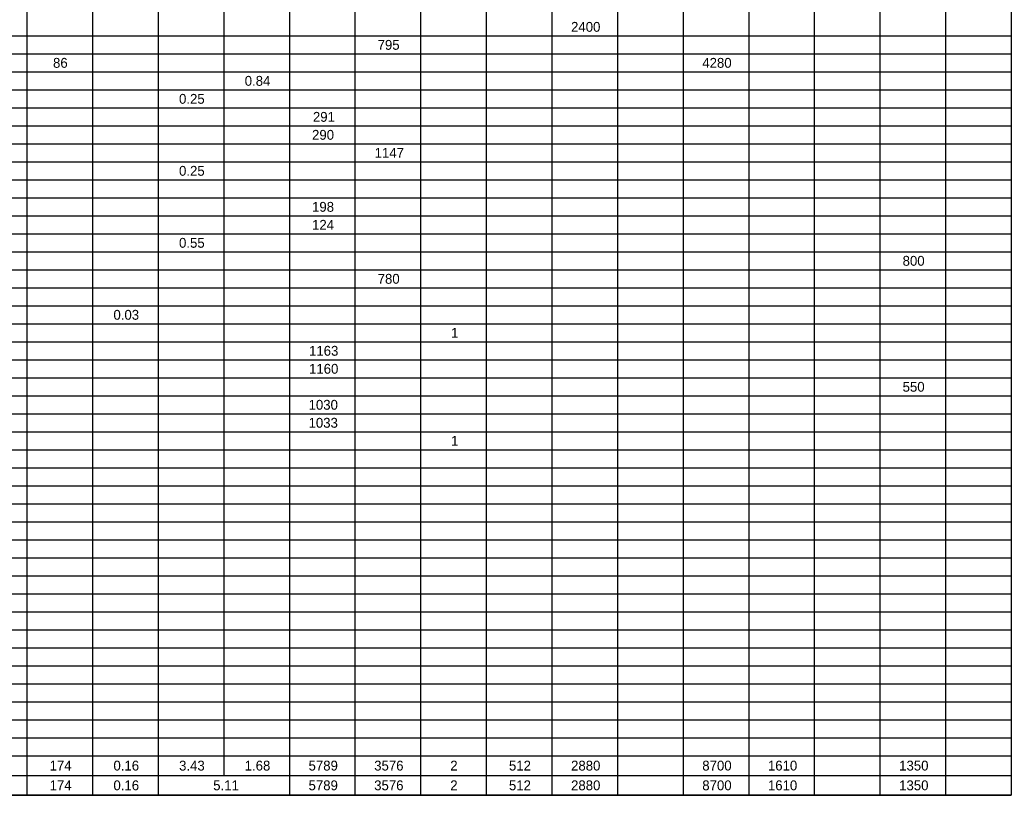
# Model space of a CAD drawing. Extents: x 91011267 to 91022583, y 37007614 to 37014266.
# Drawn here: x 91012046 to 91012802, y 37007614 to 37008206 of the extents above; entities that cross this region are included whole.
import ezdxf

# ---------------------------------------------------------------- set-up
doc = ezdxf.new("R2010")
doc.units = 0
doc.layers.add('SC_Scratch2', color=7, linetype='Continuous')
doc.layers.add('SH_Data', color=7, linetype='Continuous')

msp = doc.modelspace()

# ---------------------------------------------------------------- linework, layer by layer
at = {"layer": 'SC_Scratch2'}
msp.add_lwpolyline([(91011277.35, 37008663.81), (91012802.35, 37008663.81), (91012802.35, 37007613.81), (91011277.35, 37007613.81)], close=True, dxfattribs=at)
at = {"layer": 'SH_Data'}
for p, q in [((91012051.05, 37008289.61), (91012051.05, 37008083.53)), ((91012101.14, 37008289.61), (91012101.14, 37008083.53)), ((91012151.23, 37008289.61), (91012151.23, 37008083.53)), ((91012201.31, 37008289.61), (91012201.31, 37008083.53)), ((91012251.4, 37008289.61), (91012251.4, 37008083.53)), ((91012301.49, 37008289.61), (91012301.49, 37008083.53)), ((91012351.57, 37008289.61), (91012351.57, 37008083.53)), ((91012401.66, 37008289.61), (91012401.66, 37008083.53)), ((91012451.75, 37008289.61), (91012451.75, 37008083.53)), ((91012501.83, 37008289.61), (91012501.83, 37008083.53)), ((91012551.92, 37008289.61), (91012551.92, 37008083.53)), ((91012602, 37008289.61), (91012602, 37008083.53)), ((91012652.09, 37008289.61), (91012652.09, 37008083.53)), ((91012702.18, 37008289.61), (91012702.18, 37008083.53)), ((91012752.26, 37008289.61), (91012752.26, 37008083.53)), ((91012802.35, 37008289.61), (91012802.35, 37008083.53)), ((91012000.97, 37008193.44), (91012551.92, 37008193.44)), ((91012551.92, 37008193.44), (91012602, 37008193.44)), ((91012602, 37008193.44), (91012652.09, 37008193.44)), ((91012652.09, 37008193.44), (91012702.18, 37008193.44)), ((91012702.18, 37008193.44), (91012802.35, 37008193.44)), ((91012000.97, 37008179.7), (91012551.92, 37008179.7)), ((91012551.92, 37008179.7), (91012602, 37008179.7)), ((91012602, 37008179.7), (91012652.09, 37008179.7)), ((91012652.09, 37008179.7), (91012702.18, 37008179.7)), ((91012702.18, 37008179.7), (91012802.35, 37008179.7)), ((91012000.97, 37008165.96), (91012551.92, 37008165.96)), ((91012551.92, 37008165.96), (91012602, 37008165.96)), ((91012602, 37008165.96), (91012652.09, 37008165.96)), ((91012652.09, 37008165.96), (91012702.18, 37008165.96)), ((91012702.18, 37008165.96), (91012802.35, 37008165.96)), ((91012000.97, 37008152.22), (91012551.92, 37008152.22)), ((91012551.92, 37008152.22), (91012602, 37008152.22)), ((91012602, 37008152.22), (91012652.09, 37008152.22)), ((91012652.09, 37008152.22), (91012702.18, 37008152.22)), ((91012702.18, 37008152.22), (91012802.35, 37008152.22)), ((91012000.97, 37008138.48), (91012551.92, 37008138.48)), ((91012551.92, 37008138.48), (91012602, 37008138.48)), ((91012602, 37008138.48), (91012652.09, 37008138.48)), ((91012652.09, 37008138.48), (91012702.18, 37008138.48)), ((91012702.18, 37008138.48), (91012802.35, 37008138.48)), ((91012000.97, 37008124.75), (91012551.92, 37008124.75)), ((91012551.92, 37008124.75), (91012602, 37008124.75)), ((91012602, 37008124.75), (91012652.09, 37008124.75)), ((91012652.09, 37008124.75), (91012702.18, 37008124.75)), ((91012702.18, 37008124.75), (91012802.35, 37008124.75)), ((91012000.97, 37008111.01), (91012551.92, 37008111.01)), ((91012551.92, 37008111.01), (91012602, 37008111.01)), ((91012602, 37008111.01), (91012652.09, 37008111.01)), ((91012652.09, 37008111.01), (91012702.18, 37008111.01)), ((91012702.18, 37008111.01), (91012802.35, 37008111.01)), ((91012000.97, 37008097.27), (91012551.92, 37008097.27)), ((91012551.92, 37008097.27), (91012602, 37008097.27)), ((91012602, 37008097.27), (91012652.09, 37008097.27)), ((91012652.09, 37008097.27), (91012702.18, 37008097.27)), ((91012702.18, 37008097.27), (91012802.35, 37008097.27)), ((91012000.97, 37008083.53), (91012551.92, 37008083.53)), ((91012051.05, 37008083.53), (91012051.05, 37008069.79)), ((91012101.14, 37008083.53), (91012101.14, 37008069.79)), ((91012151.23, 37008083.53), (91012151.23, 37008069.79)), ((91012201.31, 37008083.53), (91012201.31, 37008069.79)), ((91012251.4, 37008083.53), (91012251.4, 37008069.79)), ((91012301.49, 37008083.53), (91012301.49, 37008069.79)), ((91012351.57, 37008083.53), (91012351.57, 37008069.79)), ((91012401.66, 37008083.53), (91012401.66, 37008069.79)), ((91012451.75, 37008083.53), (91012451.75, 37008069.79)), ((91012501.83, 37008083.53), (91012501.83, 37008069.79)), ((91012551.92, 37008083.53), (91012602, 37008083.53)), ((91012551.92, 37008083.53), (91012551.92, 37008069.79)), ((91012602, 37008083.53), (91012652.09, 37008083.53)), ((91012602, 37008083.53), (91012602, 37008069.79)), ((91012652.09, 37008083.53), (91012702.18, 37008083.53)), ((91012652.09, 37008083.53), (91012652.09, 37008069.79)), ((91012702.18, 37008083.53), (91012802.35, 37008083.53)), ((91012702.18, 37008083.53), (91012702.18, 37008069.79)), ((91012752.26, 37008083.53), (91012752.26, 37008069.79)), ((91012802.35, 37008083.53), (91012802.35, 37008069.79)), ((91012000.97, 37008069.79), (91012551.92, 37008069.79)), ((91012051.05, 37008069.79), (91012051.05, 37008056.05)), ((91012101.14, 37008069.79), (91012101.14, 37008056.05)), ((91012151.23, 37008069.79), (91012151.23, 37008056.05)), ((91012201.31, 37008069.79), (91012201.31, 37008056.05)), ((91012251.4, 37008069.79), (91012251.4, 37008056.05)), ((91012301.49, 37008069.79), (91012301.49, 37008056.05)), ((91012351.57, 37008069.79), (91012351.57, 37008056.05)), ((91012401.66, 37008069.79), (91012401.66, 37008056.05)), ((91012451.75, 37008069.79), (91012451.75, 37008056.05)), ((91012501.83, 37008069.79), (91012501.83, 37008056.05)), ((91012551.92, 37008069.79), (91012602, 37008069.79)), ((91012551.92, 37008069.79), (91012551.92, 37008056.05)), ((91012602, 37008069.79), (91012652.09, 37008069.79)), ((91012602, 37008069.79), (91012602, 37008056.05)), ((91012652.09, 37008069.79), (91012702.18, 37008069.79)), ((91012652.09, 37008069.79), (91012652.09, 37008056.05)), ((91012702.18, 37008069.79), (91012802.35, 37008069.79)), ((91012702.18, 37008069.79), (91012702.18, 37008056.05)), ((91012752.26, 37008069.79), (91012752.26, 37008056.05)), ((91012802.35, 37008069.79), (91012802.35, 37008056.05)), ((91012000.97, 37008056.05), (91012551.92, 37008056.05)), ((91012051.05, 37008056.05), (91012051.05, 37008014.84)), ((91012101.14, 37008056.05), (91012101.14, 37008014.84)), ((91012151.23, 37008056.05), (91012151.23, 37008014.84)), ((91012201.31, 37008056.05), (91012201.31, 37008014.84)), ((91012251.4, 37008056.05), (91012251.4, 37008014.84)), ((91012301.49, 37008056.05), (91012301.49, 37008014.84)), ((91012351.57, 37008056.05), (91012351.57, 37008014.84)), ((91012401.66, 37008056.05), (91012401.66, 37008014.84)), ((91012451.75, 37008056.05), (91012451.75, 37008014.84)), ((91012501.83, 37008056.05), (91012501.83, 37008014.84)), ((91012551.92, 37008056.05), (91012602, 37008056.05)), ((91012551.92, 37008056.05), (91012551.92, 37008014.84)), ((91012602, 37008056.05), (91012652.09, 37008056.05)), ((91012602, 37008056.05), (91012602, 37008014.84)), ((91012652.09, 37008056.05), (91012702.18, 37008056.05)), ((91012652.09, 37008056.05), (91012652.09, 37008014.84)), ((91012702.18, 37008056.05), (91012802.35, 37008056.05)), ((91012702.18, 37008056.05), (91012702.18, 37008014.84)), ((91012752.26, 37008056.05), (91012752.26, 37008014.84)), ((91012802.35, 37008056.05), (91012802.35, 37008014.84)), ((91012000.97, 37008042.32), (91012551.92, 37008042.32)), ((91012551.92, 37008042.32), (91012602, 37008042.32)), ((91012602, 37008042.32), (91012652.09, 37008042.32)), ((91012652.09, 37008042.32), (91012702.18, 37008042.32)), ((91012702.18, 37008042.32), (91012802.35, 37008042.32)), ((91012000.97, 37008028.58), (91012551.92, 37008028.58)), ((91012551.92, 37008028.58), (91012602, 37008028.58)), ((91012602, 37008028.58), (91012652.09, 37008028.58)), ((91012652.09, 37008028.58), (91012702.18, 37008028.58)), ((91012702.18, 37008028.58), (91012802.35, 37008028.58)), ((91012000.97, 37008014.84), (91012551.92, 37008014.84)), ((91012051.05, 37008014.84), (91012051.05, 37008001.1)), ((91012101.14, 37008014.84), (91012101.14, 37008001.1)), ((91012151.23, 37008014.84), (91012151.23, 37008001.1)), ((91012201.31, 37008014.84), (91012201.31, 37008001.1)), ((91012251.4, 37008014.84), (91012251.4, 37008001.1)), ((91012301.49, 37008014.84), (91012301.49, 37008001.1)), ((91012351.57, 37008014.84), (91012351.57, 37008001.1)), ((91012401.66, 37008014.84), (91012401.66, 37008001.1)), ((91012451.75, 37008014.84), (91012451.75, 37008001.1)), ((91012501.83, 37008014.84), (91012501.83, 37008001.1)), ((91012551.92, 37008014.84), (91012602, 37008014.84)), ((91012551.92, 37008014.84), (91012551.92, 37008001.1)), ((91012602, 37008014.84), (91012652.09, 37008014.84)), ((91012602, 37008014.84), (91012602, 37008001.1)), ((91012652.09, 37008014.84), (91012702.18, 37008014.84)), ((91012652.09, 37008014.84), (91012652.09, 37008001.1)), ((91012702.18, 37008014.84), (91012802.35, 37008014.84)), ((91012702.18, 37008014.84), (91012702.18, 37008001.1)), ((91012752.26, 37008014.84), (91012752.26, 37008001.1)), ((91012802.35, 37008014.84), (91012802.35, 37008001.1)), ((91012000.97, 37008001.1), (91012551.92, 37008001.1)), ((91012051.05, 37008001.1), (91012051.05, 37007987.36)), ((91012101.14, 37008001.1), (91012101.14, 37007987.36)), ((91012151.23, 37008001.1), (91012151.23, 37007987.36)), ((91012201.31, 37008001.1), (91012201.31, 37007987.36)), ((91012251.4, 37008001.1), (91012251.4, 37007987.36)), ((91012301.49, 37008001.1), (91012301.49, 37007987.36)), ((91012351.57, 37008001.1), (91012351.57, 37007987.36)), ((91012401.66, 37008001.1), (91012401.66, 37007987.36)), ((91012451.75, 37008001.1), (91012451.75, 37007987.36)), ((91012501.83, 37008001.1), (91012501.83, 37007987.36)), ((91012551.92, 37008001.1), (91012602, 37008001.1)), ((91012551.92, 37008001.1), (91012551.92, 37007987.36)), ((91012602, 37008001.1), (91012652.09, 37008001.1)), ((91012602, 37008001.1), (91012602, 37007987.36)), ((91012652.09, 37008001.1), (91012702.18, 37008001.1)), ((91012652.09, 37008001.1), (91012652.09, 37007987.36)), ((91012702.18, 37008001.1), (91012802.35, 37008001.1)), ((91012702.18, 37008001.1), (91012702.18, 37007987.36)), ((91012752.26, 37008001.1), (91012752.26, 37007987.36)), ((91012802.35, 37008001.1), (91012802.35, 37007987.36)), ((91012000.97, 37007987.36), (91012551.92, 37007987.36)), ((91012051.05, 37007987.36), (91012051.05, 37007946.15)), ((91012101.14, 37007987.36), (91012101.14, 37007946.15)), ((91012151.23, 37007987.36), (91012151.23, 37007946.15)), ((91012201.31, 37007987.36), (91012201.31, 37007946.15)), ((91012251.4, 37007987.36), (91012251.4, 37007946.15)), ((91012301.49, 37007987.36), (91012301.49, 37007946.15)), ((91012351.57, 37007987.36), (91012351.57, 37007946.15)), ((91012401.66, 37007987.36), (91012401.66, 37007946.15)), ((91012451.75, 37007987.36), (91012451.75, 37007946.15)), ((91012501.83, 37007987.36), (91012501.83, 37007946.15)), ((91012551.92, 37007987.36), (91012602, 37007987.36)), ((91012551.92, 37007987.36), (91012551.92, 37007946.15)), ((91012602, 37007987.36), (91012652.09, 37007987.36)), ((91012602, 37007987.36), (91012602, 37007946.15)), ((91012652.09, 37007987.36), (91012702.18, 37007987.36)), ((91012652.09, 37007987.36), (91012652.09, 37007946.15)), ((91012702.18, 37007987.36), (91012802.35, 37007987.36)), ((91012702.18, 37007987.36), (91012702.18, 37007946.15)), ((91012752.26, 37007987.36), (91012752.26, 37007946.15)), ((91012802.35, 37007987.36), (91012802.35, 37007946.15)), ((91012000.97, 37007973.62), (91012551.92, 37007973.62)), ((91012551.92, 37007973.62), (91012602, 37007973.62)), ((91012602, 37007973.62), (91012652.09, 37007973.62)), ((91012652.09, 37007973.62), (91012702.18, 37007973.62)), ((91012702.18, 37007973.62), (91012802.35, 37007973.62)), ((91012000.97, 37007959.89), (91012551.92, 37007959.89)), ((91012551.92, 37007959.89), (91012602, 37007959.89)), ((91012602, 37007959.89), (91012652.09, 37007959.89)), ((91012652.09, 37007959.89), (91012702.18, 37007959.89)), ((91012702.18, 37007959.89), (91012802.35, 37007959.89)), ((91012000.97, 37007946.15), (91012551.92, 37007946.15)), ((91012051.05, 37007946.15), (91012051.05, 37007932.41)), ((91012101.14, 37007946.15), (91012101.14, 37007932.41)), ((91012151.23, 37007946.15), (91012151.23, 37007932.41)), ((91012201.31, 37007946.15), (91012201.31, 37007932.41)), ((91012251.4, 37007946.15), (91012251.4, 37007932.41)), ((91012301.49, 37007946.15), (91012301.49, 37007932.41)), ((91012351.57, 37007946.15), (91012351.57, 37007932.41)), ((91012401.66, 37007946.15), (91012401.66, 37007932.41)), ((91012451.75, 37007946.15), (91012451.75, 37007932.41)), ((91012501.83, 37007946.15), (91012501.83, 37007932.41)), ((91012551.92, 37007946.15), (91012602, 37007946.15)), ((91012551.92, 37007946.15), (91012551.92, 37007932.41)), ((91012602, 37007946.15), (91012652.09, 37007946.15)), ((91012602, 37007946.15), (91012602, 37007932.41)), ((91012652.09, 37007946.15), (91012702.18, 37007946.15)), ((91012652.09, 37007946.15), (91012652.09, 37007932.41)), ((91012702.18, 37007946.15), (91012802.35, 37007946.15)), ((91012702.18, 37007946.15), (91012702.18, 37007932.41)), ((91012752.26, 37007946.15), (91012752.26, 37007932.41)), ((91012802.35, 37007946.15), (91012802.35, 37007932.41)), ((91012000.97, 37007932.41), (91012551.92, 37007932.41)), ((91012051.05, 37007932.41), (91012051.05, 37007918.67)), ((91012101.14, 37007932.41), (91012101.14, 37007918.67)), ((91012151.23, 37007932.41), (91012151.23, 37007918.67)), ((91012201.31, 37007932.41), (91012201.31, 37007918.67)), ((91012251.4, 37007932.41), (91012251.4, 37007918.67)), ((91012301.49, 37007932.41), (91012301.49, 37007918.67)), ((91012351.57, 37007932.41), (91012351.57, 37007918.67)), ((91012401.66, 37007932.41), (91012401.66, 37007918.67)), ((91012451.75, 37007932.41), (91012451.75, 37007918.67)), ((91012501.83, 37007932.41), (91012501.83, 37007918.67)), ((91012551.92, 37007932.41), (91012602, 37007932.41)), ((91012551.92, 37007932.41), (91012551.92, 37007918.67)), ((91012602, 37007932.41), (91012652.09, 37007932.41)), ((91012602, 37007932.41), (91012602, 37007918.67)), ((91012652.09, 37007932.41), (91012702.18, 37007932.41)), ((91012652.09, 37007932.41), (91012652.09, 37007918.67)), ((91012702.18, 37007932.41), (91012802.35, 37007932.41)), ((91012702.18, 37007932.41), (91012702.18, 37007918.67)), ((91012752.26, 37007932.41), (91012752.26, 37007918.67)), ((91012802.35, 37007932.41), (91012802.35, 37007918.67)), ((91012000.97, 37007918.67), (91012551.92, 37007918.67)), ((91012051.05, 37007918.67), (91012051.05, 37007613.81)), ((91012101.14, 37007918.67), (91012101.14, 37007613.81)), ((91012151.23, 37007918.67), (91012151.23, 37007613.81)), ((91012201.31, 37007918.67), (91012201.31, 37007628.86)), ((91012251.4, 37007918.67), (91012251.4, 37007613.81)), ((91012301.49, 37007918.67), (91012301.49, 37007613.81)), ((91012351.57, 37007918.67), (91012351.57, 37007613.81)), ((91012401.66, 37007918.67), (91012401.66, 37007613.81)), ((91012451.75, 37007918.67), (91012451.75, 37007613.81)), ((91012501.83, 37007918.67), (91012501.83, 37007613.81)), ((91012551.92, 37007918.67), (91012602, 37007918.67)), ((91012551.92, 37007918.67), (91012551.92, 37007613.81)), ((91012602, 37007918.67), (91012652.09, 37007918.67)), ((91012602, 37007918.67), (91012602, 37007613.81)), ((91012652.09, 37007918.67), (91012702.18, 37007918.67)), ((91012652.09, 37007918.67), (91012652.09, 37007613.81)), ((91012702.18, 37007918.67), (91012802.35, 37007918.67)), ((91012702.18, 37007918.67), (91012702.18, 37007613.81)), ((91012752.26, 37007918.67), (91012752.26, 37007613.81)), ((91012802.35, 37007918.67), (91012802.35, 37007613.81)), ((91012000.97, 37007904.93), (91012551.92, 37007904.93)), ((91012551.92, 37007904.93), (91012602, 37007904.93)), ((91012602, 37007904.93), (91012652.09, 37007904.93)), ((91012652.09, 37007904.93), (91012702.18, 37007904.93)), ((91012702.18, 37007904.93), (91012802.35, 37007904.93)), ((91012000.97, 37007891.19), (91012551.92, 37007891.19)), ((91012551.92, 37007891.19), (91012602, 37007891.19)), ((91012602, 37007891.19), (91012652.09, 37007891.19)), ((91012652.09, 37007891.19), (91012702.18, 37007891.19)), ((91012702.18, 37007891.19), (91012802.35, 37007891.19)), ((91012000.97, 37007877.46), (91012551.92, 37007877.46)), ((91012551.92, 37007877.46), (91012602, 37007877.46)), ((91012602, 37007877.46), (91012652.09, 37007877.46)), ((91012652.09, 37007877.46), (91012702.18, 37007877.46)), ((91012702.18, 37007877.46), (91012802.35, 37007877.46)), ((91012000.97, 37007863.72), (91012551.92, 37007863.72)), ((91012551.92, 37007863.72), (91012602, 37007863.72)), ((91012602, 37007863.72), (91012652.09, 37007863.72)), ((91012652.09, 37007863.72), (91012702.18, 37007863.72)), ((91012702.18, 37007863.72), (91012802.35, 37007863.72)), ((91012000.97, 37007849.98), (91012551.92, 37007849.98)), ((91012551.92, 37007849.98), (91012602, 37007849.98)), ((91012602, 37007849.98), (91012652.09, 37007849.98)), ((91012652.09, 37007849.98), (91012702.18, 37007849.98)), ((91012702.18, 37007849.98), (91012802.35, 37007849.98)), ((91012000.97, 37007836.24), (91012551.92, 37007836.24)), ((91012551.92, 37007836.24), (91012602, 37007836.24)), ((91012602, 37007836.24), (91012652.09, 37007836.24)), ((91012652.09, 37007836.24), (91012702.18, 37007836.24)), ((91012702.18, 37007836.24), (91012802.35, 37007836.24)), ((91012000.97, 37007822.5), (91012551.92, 37007822.5)), ((91012551.92, 37007822.5), (91012602, 37007822.5)), ((91012602, 37007822.5), (91012652.09, 37007822.5)), ((91012652.09, 37007822.5), (91012702.18, 37007822.5)), ((91012702.18, 37007822.5), (91012802.35, 37007822.5)), ((91012000.97, 37007808.76), (91012551.92, 37007808.76)), ((91012551.92, 37007808.76), (91012602, 37007808.76)), ((91012602, 37007808.76), (91012652.09, 37007808.76)), ((91012652.09, 37007808.76), (91012702.18, 37007808.76)), ((91012702.18, 37007808.76), (91012802.35, 37007808.76)), ((91012000.97, 37007795.03), (91012551.92, 37007795.03)), ((91012551.92, 37007795.03), (91012602, 37007795.03)), ((91012602, 37007795.03), (91012652.09, 37007795.03)), ((91012652.09, 37007795.03), (91012702.18, 37007795.03)), ((91012702.18, 37007795.03), (91012802.35, 37007795.03)), ((91012000.97, 37007781.29), (91012551.92, 37007781.29)), ((91012551.92, 37007781.29), (91012602, 37007781.29)), ((91012602, 37007781.29), (91012652.09, 37007781.29)), ((91012652.09, 37007781.29), (91012702.18, 37007781.29)), ((91012702.18, 37007781.29), (91012802.35, 37007781.29)), ((91012000.97, 37007767.55), (91012551.92, 37007767.55)), ((91012551.92, 37007767.55), (91012602, 37007767.55)), ((91012602, 37007767.55), (91012652.09, 37007767.55)), ((91012652.09, 37007767.55), (91012702.18, 37007767.55)), ((91012702.18, 37007767.55), (91012802.35, 37007767.55)), ((91012000.97, 37007753.81), (91012551.92, 37007753.81)), ((91012551.92, 37007753.81), (91012602, 37007753.81)), ((91012602, 37007753.81), (91012652.09, 37007753.81)), ((91012652.09, 37007753.81), (91012702.18, 37007753.81)), ((91012702.18, 37007753.81), (91012802.35, 37007753.81)), ((91012000.97, 37007740.07), (91012551.92, 37007740.07)), ((91012551.92, 37007740.07), (91012602, 37007740.07)), ((91012602, 37007740.07), (91012652.09, 37007740.07)), ((91012652.09, 37007740.07), (91012702.18, 37007740.07)), ((91012702.18, 37007740.07), (91012802.35, 37007740.07)), ((91012000.97, 37007726.33), (91012551.92, 37007726.33)), ((91012551.92, 37007726.33), (91012602, 37007726.33)), ((91012602, 37007726.33), (91012652.09, 37007726.33)), ((91012652.09, 37007726.33), (91012702.18, 37007726.33)), ((91012702.18, 37007726.33), (91012802.35, 37007726.33)), ((91012000.97, 37007712.6), (91012551.92, 37007712.6)), ((91012551.92, 37007712.6), (91012602, 37007712.6)), ((91012602, 37007712.6), (91012652.09, 37007712.6)), ((91012652.09, 37007712.6), (91012702.18, 37007712.6)), ((91012702.18, 37007712.6), (91012802.35, 37007712.6)), ((91012000.97, 37007698.86), (91012551.92, 37007698.86)), ((91012551.92, 37007698.86), (91012602, 37007698.86)), ((91012602, 37007698.86), (91012652.09, 37007698.86)), ((91012652.09, 37007698.86), (91012702.18, 37007698.86)), ((91012702.18, 37007698.86), (91012802.35, 37007698.86)), ((91012000.97, 37007685.12), (91012551.92, 37007685.12)), ((91012551.92, 37007685.12), (91012602, 37007685.12)), ((91012602, 37007685.12), (91012652.09, 37007685.12)), ((91012652.09, 37007685.12), (91012702.18, 37007685.12)), ((91012702.18, 37007685.12), (91012802.35, 37007685.12)), ((91012000.97, 37007671.38), (91012551.92, 37007671.38)), ((91012551.92, 37007671.38), (91012602, 37007671.38)), ((91012602, 37007671.38), (91012652.09, 37007671.38)), ((91012652.09, 37007671.38), (91012702.18, 37007671.38)), ((91012702.18, 37007671.38), (91012802.35, 37007671.38)), ((91012000.97, 37007657.64), (91012551.92, 37007657.64)), ((91012551.92, 37007657.64), (91012602, 37007657.64)), ((91012602, 37007657.64), (91012652.09, 37007657.64)), ((91012652.09, 37007657.64), (91012702.18, 37007657.64)), ((91012702.18, 37007657.64), (91012802.35, 37007657.64)), ((91012000.97, 37007643.9), (91012551.92, 37007643.9)), ((91012551.92, 37007643.9), (91012602, 37007643.9)), ((91012602, 37007643.9), (91012652.09, 37007643.9)), ((91012652.09, 37007643.9), (91012702.18, 37007643.9)), ((91012702.18, 37007643.9), (91012802.35, 37007643.9)), ((91012000.97, 37007628.86), (91012551.92, 37007628.86)), ((91012551.92, 37007628.86), (91012602, 37007628.86)), ((91012602, 37007628.86), (91012652.09, 37007628.86)), ((91012652.09, 37007628.86), (91012702.18, 37007628.86)), ((91012702.18, 37007628.86), (91012802.35, 37007628.86)), ((91012000.97, 37007613.81), (91012551.92, 37007613.81)), ((91012551.92, 37007613.81), (91012602, 37007613.81)), ((91012602, 37007613.81), (91012652.09, 37007613.81)), ((91012652.09, 37007613.81), (91012702.18, 37007613.81)), ((91012702.18, 37007613.81), (91012802.35, 37007613.81))]:
    msp.add_line(p, q, dxfattribs=at)

# ---------------------------------------------------------------- texts
for s, height, p in [('2400', 7.523, (91012466.42, 37008196.54)), ('795', 7.523, (91012318.77, 37008182.81)), ('86', 7.523, (91012071.01, 37008169.07)), ('4280', 7.523, (91012566.59, 37008169.07)), ('0.84', 7.523, (91012217.32, 37008155.33)), ('0.25', 7.523, (91012167.19, 37008141.59)), ('291', 7.523, (91012269.37, 37008127.85)), ('290', 7.523, (91012268.72, 37008114.12)), ('1147', 7.523, (91012316.5, 37008100.38)), ('0.25', 7.523, (91012167.19, 37008086.64)), ('198', 7.523, (91012268.71, 37008059.16)), ('124', 7.523, (91012268.73, 37008045.42)), ('0.55', 7.523, (91012167.19, 37008031.69)), ('800', 7.523, (91012719.5, 37008017.95)), ('780', 7.523, (91012318.81, 37008004.21)), ('0.03', 7.523, (91012117.13, 37007976.73)), ('1', 7.52, (91012374.84, 37007962.99)), ('1163', 7.523, (91012266.42, 37007949.26)), ('1160', 7.523, (91012266.43, 37007935.52)), ('550', 7.523, (91012719.5, 37007921.78)), ('1030', 7.523, (91012266.08, 37007908.04)), ('1033', 7.523, (91012266.06, 37007894.3)), ('1', 7.52, (91012374.84, 37007880.56)), ('174', 7.523, (91012068.38, 37007632.62)), ('0.16', 7.523, (91012117.13, 37007632.62)), ('3.43', 7.523, (91012167.22, 37007632.62)), ('1.68', 7.523, (91012217.3, 37007632.62)), ('5789', 7.523, (91012266.06, 37007632.62)), ('3576', 7.523, (91012316.15, 37007632.62)), ('2', 7.52, (91012374.22, 37007632.62)), ('512', 7.523, (91012419.01, 37007632.62)), ('2880', 7.523, (91012466.42, 37007632.62)), ('8700', 7.523, (91012566.59, 37007632.62)), ('1610', 7.523, (91012616.68, 37007632.62)), ('1350', 7.523, (91012716.85, 37007632.62)), ('174', 7.523, (91012068.38, 37007617.57)), ('0.16', 7.523, (91012117.13, 37007617.57)), ('5.11', 7.523, (91012193.27, 37007617.57)), ('5789', 7.523, (91012266.06, 37007617.57)), ('3576', 7.523, (91012316.15, 37007617.57)), ('2', 7.52, (91012374.22, 37007617.57)), ('512', 7.523, (91012419.01, 37007617.57)), ('2880', 7.523, (91012466.42, 37007617.57)), ('8700', 7.523, (91012566.59, 37007617.57)), ('1610', 7.523, (91012616.68, 37007617.57)), ('1350', 7.523, (91012716.85, 37007617.57))]:
    msp.add_text(s, height=height, dxfattribs=at).set_placement(p)

doc.saveas('drawing.dxf')
